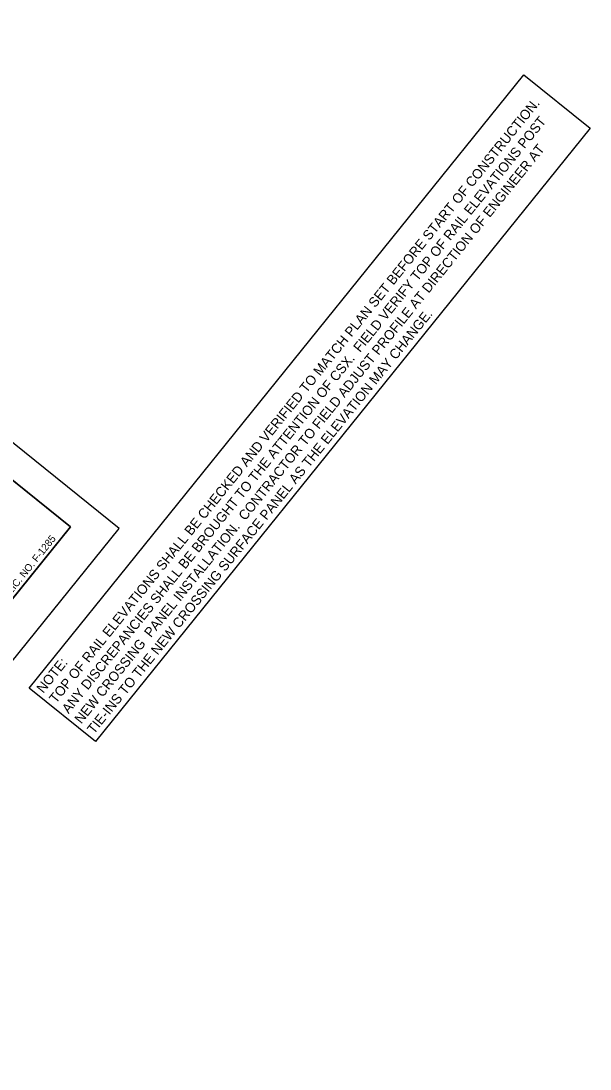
# Model space of a CAD drawing. Extents: x 1487832 to 1490056, y 498345 to 500343.
# Drawn here: x 1489728 to 1490056, y 499344 to 499948 of the extents above; entities that cross this region are included whole.
import ezdxf

# ---------------------------------------------------------------- set-up
doc = ezdxf.new("R2010")
doc.units = 0
for name, color, linetype in [('Prop Grid Mask', 7, 'Continuous'), ('Prop Horizontal Alignment Curve and Spiral Data', 7, 'Continuous'), ('Sheet Clip Boundary CELL', 7, 'Continuous'), ('Sheet Plan CELL', 7, 'Continuous'), ('Sheet Plot Border Outside CELL', 7, 'Continuous')]:
    doc.layers.add(name, color=color, linetype=linetype)

msp = doc.modelspace()

# ---------------------------------------------------------------- linework, layer by layer
at = {"layer": 'Prop Grid Mask'}
for points in [[(1489732.5, 499563.73), (1490017.53, 499917.17), (1490055.6, 499886.47), (1489770.57, 499533.03)], [(1489652, 499610.52), (1489715.61, 499689.4), (1489756.18, 499656.68), (1489692.57, 499577.8)]]:
    msp.add_lwpolyline(points, close=True, dxfattribs=at)
at = {"layer": 'Sheet Clip Boundary CELL'}
msp.add_lwpolyline([(1488948.36, 500051.16), (1488813.25, 500160.1), (1488087.84, 499260.53), (1488879.09, 498569.08), (1489756.18, 499656.68), (1489073.94, 500206.87)], close=True, dxfattribs=at)
at = {"layer": 'Sheet Plan CELL'}
for points in [[(1488938.86, 500315.83), (1487997.21, 499148.18), (1488814.55, 498489.05), (1489756.18, 499656.68)], [(1488814.55, 498489.05), (1487997.21, 499148.15), (1488813.25, 500160.1), (1488930.07, 500065.91), (1489055.66, 500221.61), (1489756.18, 499656.68)]]:
    msp.add_lwpolyline(points, close=True, dxfattribs=at)
at = {"layer": 'Sheet Plot Border Outside CELL'}
msp.add_lwpolyline([(1488727.56, 498345.32), (1489784.38, 499655.78), (1488932.01, 500343.17), (1487875.19, 499032.7)], close=True, dxfattribs=at)

# ---------------------------------------------------------------- texts
at = {"layer": 'Prop Grid Mask'}
msp.add_text('919.223.8965   NC LIC. NO. F-1285', height=4.1773, rotation=51.11565, dxfattribs=at).set_placement((1489691.95, 499580.2))
at = {"layer": 'Prop Horizontal Alignment Curve and Spiral Data'}
for s, p in [('TOP OF RAIL ELEVATIONS SHALL BE CHECKED AND VERIFIED TO MATCH PLAN SET BEFORE START OF CONSTRUCTION.', (1489747.86, 499554.6)), ('ANY DISCREPANCIES SHALL BE BROUGHT TO THE ATTENTION OF CSX.  FIELD VERIFY TOP OF RAIL ELEVATIONS POST ', (1489755.16, 499548.71)), ('NEW CROSSING  PANEL INSTALLATION.  CONTRACTOR TO FIELD ADJUST PROFILE AT DIRECTION OF ENGINEER AT ', (1489762.45, 499542.82)), ('TIE-INS TO THE NEW CROSSING SURFACE PANEL AS THE ELEVATION MAY CHANGE.', (1489769.75, 499536.94)), ('NOTE:', (1489740.56, 499560.48))]:
    msp.add_text(s, height=5.625, rotation=51.11556, dxfattribs=at).set_placement(p)

doc.saveas('drawing.dxf')
